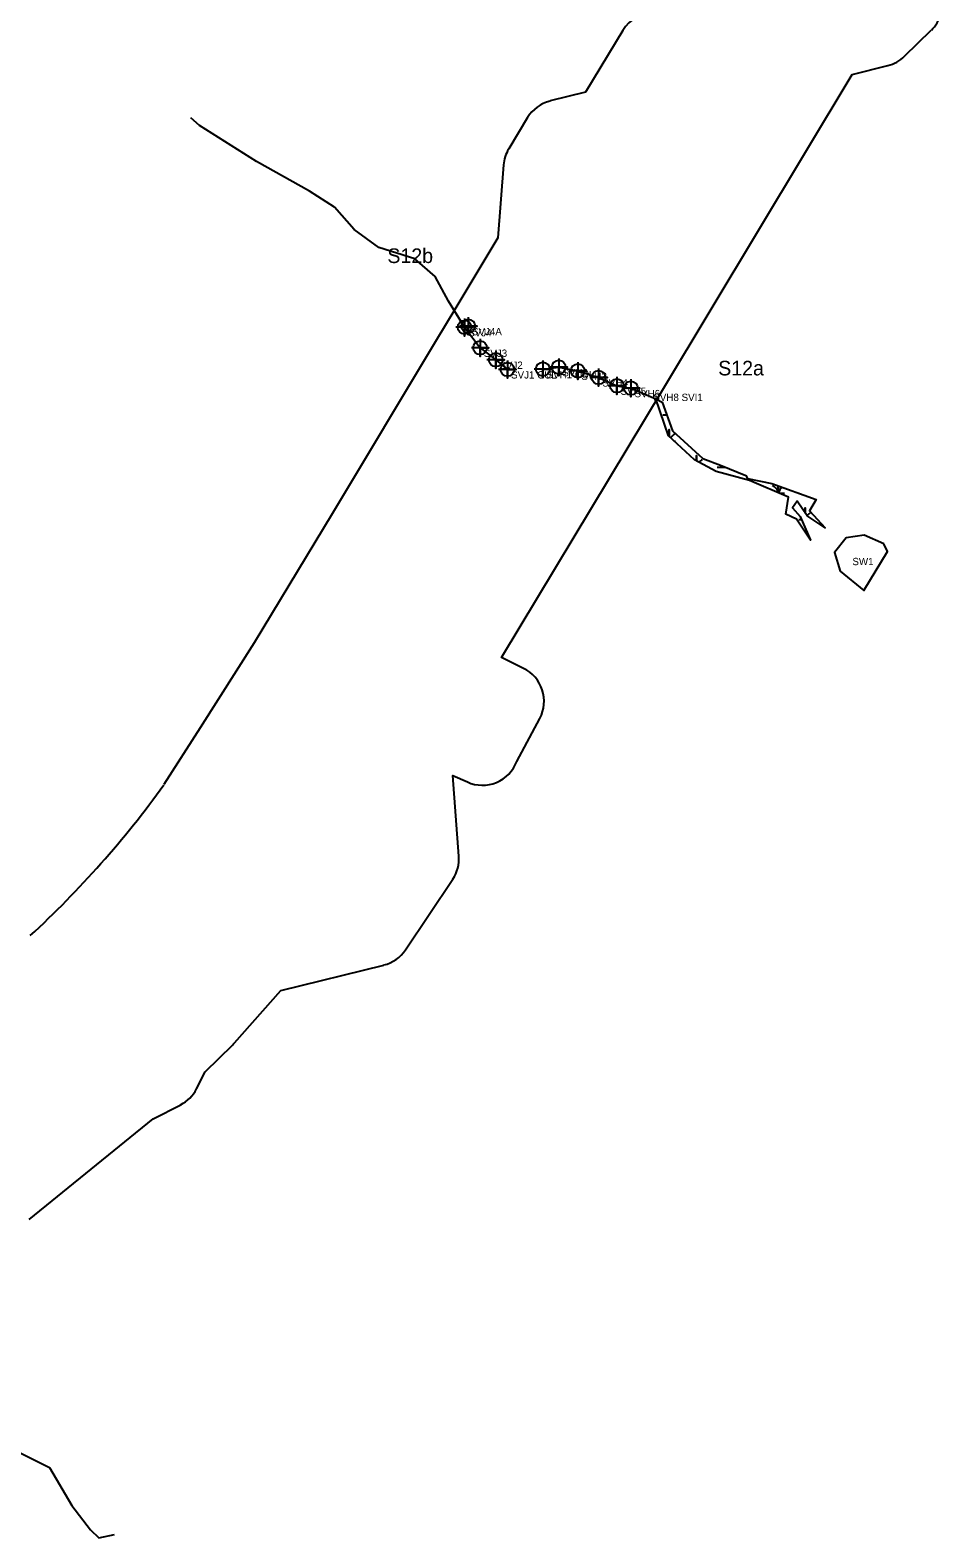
# Model space of a CAD drawing. Extents: x 1253697 to 1278588, y 912189 to 981699.
# Drawn here: x 1261249 to 1262493, y 917455 to 919517 of the extents above; entities that cross this region are included whole.
import ezdxf

# ---------------------------------------------------------------- set-up
doc = ezdxf.new("R2010")
doc.units = 0
for name, color, linetype in [('Default', 7, 'Continuous'), ('Exist Environmental Wetland Boundary', 7, 'Continuous'), ('Exist Hydro Jurisdictional Stream or Body of Water Mitigable', 7, 'Continuous'), ('Exist Hydro Jurisdictional Stream or Body of Water Mitigable Cogo Comment', 7, 'Continuous'), ('Exist Hydro Jurisdictional Stream or Body of Water Mitigable Cogo Number', 7, 'Continuous'), ('Exist Hydro Jurisdictional Stream or Body of Water Mitigable Cogo Point CELL', 7, 'Continuous')]:
    doc.layers.add(name, color=color, linetype=linetype)

msp = doc.modelspace()

# ---------------------------------------------------------------- linework, layer by layer
at = {"layer": 'Default'}
for p, q in [((1262443.9, 919481.7), (1262480.5, 919517.4)), ((1262443.9, 919481.7), (1262480.5, 919517.4)), ((1262443.9, 919481.7), (1262480.5, 919517.4)), ((1262443.9, 919481.7), (1262480.5, 919517.4)), ((1261928.6, 919397.8), (1261902.9, 919355)), ((1261928.6, 919397.8), (1261902.9, 919355)), ((1261928.6, 919397.8), (1261902.9, 919355)), ((1261928.6, 919397.8), (1261902.9, 919355)), ((1261913.9, 918517.1), (1261945.3, 918576.1)), ((1261913.9, 918517.1), (1261945.3, 918576.1)), ((1261913.9, 918517.1), (1261945.3, 918576.1)), ((1261913.9, 918517.1), (1261945.3, 918576.1)), ((1261481.1, 918563.1), (1261431.6, 918485.5)), ((1261481.1, 918563.1), (1261431.6, 918485.5)), ((1261481.1, 918563.1), (1261431.6, 918485.5)), ((1261481.1, 918563.1), (1261431.6, 918485.5)), ((1261761.8, 918259.6), (1261826.4, 918356.4)), ((1261761.8, 918259.6), (1261826.4, 918356.4)), ((1261761.8, 918259.6), (1261826.4, 918356.4)), ((1261761.8, 918259.6), (1261826.4, 918356.4))]:
    msp.add_line(p, q, dxfattribs=at)
for points in [[(1262058.7, 919517.1), (1262007.9, 919432.7), (1261959.4, 919420.6)], [(1262058.7, 919517.1), (1262007.9, 919432.7), (1261959.4, 919420.6)], [(1262058.7, 919517.1), (1262007.9, 919432.7), (1261959.4, 919420.6)], [(1262058.7, 919517.1), (1262007.9, 919432.7), (1261959.4, 919420.6)], [(1261923.1, 918644.5), (1261893, 918659.2), (1262114.3, 919027.3), (1262372.5, 919456.9), (1262421, 919469)], [(1261923.1, 918644.5), (1261893, 918659.2), (1262114.3, 919027.3), (1262372.5, 919456.9), (1262421, 919469)], [(1261923.1, 918644.5), (1261893, 918659.2), (1262114.3, 919027.3), (1262372.5, 919456.9), (1262421, 919469)], [(1261923.1, 918644.5), (1261893, 918659.2), (1262114.3, 919027.3), (1262372.5, 919456.9), (1262421, 919469)], [(1261895.9, 919333.1), (1261888.1, 919233.4), (1261830.5, 919137.5)], [(1261895.9, 919333.1), (1261888.1, 919233.4), (1261830.5, 919137.5)], [(1261895.9, 919333.1), (1261888.1, 919233.4), (1261830.5, 919137.5)], [(1261895.9, 919333.1), (1261888.1, 919233.4), (1261830.5, 919137.5)], [(1261830.5, 919137.5), (1261802.8, 919091.4), (1261661.4, 918856.1), (1261555.1, 918679.4), (1261481.1, 918563.1)], [(1261830.5, 919137.5), (1261802.8, 919091.4), (1261661.4, 918856.1), (1261555.1, 918679.4), (1261481.1, 918563.1)], [(1261830.5, 919137.5), (1261802.8, 919091.4), (1261661.4, 918856.1), (1261555.1, 918679.4), (1261481.1, 918563.1)], [(1261830.5, 919137.5), (1261802.8, 919091.4), (1261661.4, 918856.1), (1261555.1, 918679.4), (1261481.1, 918563.1)], [(1261834.7, 918387.9), (1261826.6, 918498.2), (1261846.4, 918489.2)], [(1261834.7, 918387.9), (1261826.6, 918498.2), (1261846.4, 918489.2)], [(1261834.7, 918387.9), (1261826.6, 918498.2), (1261846.4, 918489.2)], [(1261834.7, 918387.9), (1261826.6, 918498.2), (1261846.4, 918489.2)], [(1261528.1, 918132.2), (1261591.5, 918204), (1261732.2, 918238.8)], [(1261528.1, 918132.2), (1261591.5, 918204), (1261732.2, 918238.8)], [(1261528.1, 918132.2), (1261591.5, 918204), (1261732.2, 918238.8)], [(1261528.1, 918132.2), (1261591.5, 918204), (1261732.2, 918238.8)], [(1261476.1, 918069.4), (1261488.1, 918092.6), (1261525.7, 918129.7)], [(1261476.1, 918069.4), (1261488.1, 918092.6), (1261525.7, 918129.7)], [(1261476.1, 918069.4), (1261488.1, 918092.6), (1261525.7, 918129.7)], [(1261476.1, 918069.4), (1261488.1, 918092.6), (1261525.7, 918129.7)], [(1261247.4, 917890.8), (1261416.8, 918028.6), (1261454.5, 918047.8)], [(1261247.4, 917890.8), (1261416.8, 918028.6), (1261454.5, 918047.8)], [(1261247.4, 917890.8), (1261416.8, 918028.6), (1261454.5, 918047.8)], [(1261247.4, 917890.8), (1261416.8, 918028.6), (1261454.5, 918047.8)]]:
    msp.add_lwpolyline(points, dxfattribs=at)
for centre, radius, start, end in [((1262101.6, 919491.4), 50, 88.969, 148.9907), ((1262101.6, 919491.4), 50, 88.969, 148.9907), ((1262101.6, 919491.4), 50, 88.969, 148.9907), ((1262101.6, 919491.4), 50, 88.969, 148.9907), ((1262445.6, 919553.2), 50, 314.297, 343.4141), ((1262445.6, 919553.2), 50, 314.297, 343.4141), ((1262445.6, 919553.2), 50, 314.297, 343.4141), ((1262445.6, 919553.2), 50, 314.297, 343.4141), ((1262408.9, 919517.5), 50, 283.9905, 314.297), ((1262408.9, 919517.5), 50, 283.9905, 314.297), ((1262408.9, 919517.5), 50, 283.9905, 314.297), ((1262408.9, 919517.5), 50, 283.9905, 314.297), ((1261971.5, 919372), 50, 103.9905, 148.9905), ((1261971.5, 919372), 50, 103.9905, 148.9905), ((1261971.5, 919372), 50, 103.9905, 148.9905), ((1261971.5, 919372), 50, 103.9905, 148.9905), ((1261945.7, 919329.2), 50, 148.9905, 175.5557), ((1261945.7, 919329.2), 50, 148.9905, 175.5557), ((1261945.7, 919329.2), 50, 148.9905, 175.5557), ((1261945.7, 919329.2), 50, 148.9905, 175.5557), ((1261873.4, 919111.8), 50, 148.9905, 148.9908), ((1261873.4, 919111.8), 50, 148.9905, 148.9908), ((1261901.2, 918599.6), 50, 331.9389, 64.0284), ((1261901.2, 918599.6), 50, 331.9389, 64.0284), ((1261901.2, 918599.6), 50, 331.9389, 64.0284), ((1261901.2, 918599.6), 50, 331.9389, 64.0284), ((1261523.2, 918536.3), 50, 147.48918145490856, 147.48922457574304), ((1261523.2, 918536.3), 50, 147.48918145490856, 147.48922457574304), ((1261867.1, 918534.7), 50, 245.6021, 339.4199), ((1261867.1, 918534.7), 50, 245.6021, 339.4199), ((1261867.1, 918534.7), 50, 245.6021, 339.4199), ((1261867.1, 918534.7), 50, 245.6021, 339.4199), ((1260334.6, 919272.3), 1350, 312.6253, 324.3503), ((1260334.6, 919272.3), 1350, 312.6253, 324.3503), ((1260334.6, 919272.3), 1350, 312.6253, 324.3503), ((1260334.6, 919272.3), 1350, 312.6253, 324.3503), ((1261784.9, 918384.2), 50, 326.2609, 4.2006), ((1261784.9, 918384.2), 50, 326.2609, 4.2006), ((1261784.9, 918384.2), 50, 326.2609, 4.2006), ((1261784.9, 918384.2), 50, 326.2609, 4.2006), ((1261720.2, 918287.4), 50, 283.9003, 326.2609), ((1261720.2, 918287.4), 50, 283.9003, 326.2609), ((1261720.2, 918287.4), 50, 283.9003, 326.2609), ((1261720.2, 918287.4), 50, 283.9003, 326.2609), ((1261490.6, 918165.3), 50, 314.6181, 318.5291), ((1261490.6, 918165.3), 50, 314.6181, 318.5291), ((1261490.6, 918165.3), 50, 314.6181, 318.5291), ((1261490.6, 918165.3), 50, 314.6181, 318.5291), ((1261431.7, 918092.3), 50, 297.0927, 332.7249), ((1261431.7, 918092.3), 50, 297.0927, 332.7249), ((1261431.7, 918092.3), 50, 297.0927, 332.7249), ((1261431.7, 918092.3), 50, 297.0927, 332.7249)]:
    msp.add_arc(centre, radius, start, end, dxfattribs=at)
at = {"layer": 'Exist Environmental Wetland Boundary'}
for p, q in [((1262113.6, 918991.3), (1262118.8, 918991.3)), ((1262129, 918955.5), (1262130.8, 918955.5)), ((1262271, 918885), (1262271, 918894.4)), ((1262271, 918894.4), (1262271, 918885)), ((1262273.4, 918884), (1262279.6, 918884)), ((1262299.6, 918884), (1262299.8, 918884)), ((1262299.6, 918848.2), (1262303.1, 918848.2))]:
    msp.add_line(p, q, dxfattribs=at)
msp.add_lwpolyline([(1262104, 919013.2), (1262112.5, 919008.5), (1262126.9, 918969.2), (1262168, 918931.8), (1262192.3, 918922.4), (1262227.1, 918908.4), (1262229.2, 918904.4), (1262262.4, 918897.5), (1262323.1, 918875.5), (1262314.2, 918859.8), (1262335.2, 918836.7), (1262310.6, 918853.3), (1262297.2, 918873.2), (1262290.7, 918864.2), (1262301.3, 918852.2), (1262315.5, 918820.1), (1262296.2, 918848.7), (1262281.7, 918855.3), (1262285.3, 918878.9), (1262232.1, 918901.5), (1262186.4, 918913.8), (1262156.6, 918929.8), (1262121.4, 918962.6)], close=True, dxfattribs=at)
for points in [[(1262122.2, 918961.8), (1262122.2, 918971.3), (1262122.2, 918961.8)], [(1262159.4, 918928.3), (1262159.4, 918935.5), (1262159.4, 918928.3)], [(1262188, 918919.7), (1262196.6, 918919.7), (1262196.6, 918920.7)], [(1262196.6, 918920.7), (1262196.6, 918919.7), (1262199, 918919.7)], [(1262308.2, 918856.8), (1262308.2, 918864), (1262308.2, 918856.8)]]:
    msp.add_lwpolyline(points, dxfattribs=at)
for centre, radius, start, end in [((1262109.9, 918990.4), 12.3, 65.334, 67.535), ((1262140.5, 918949.5), 19.2, 122.1274, 147.1173), ((1262177.7, 918913.7), 19.2, 122.1274, 139.0127), ((1262184.4, 918918.8), 12.3, 4.1403, 8.8357), ((1262214.9, 918913.7), 19.2, 158.9798, 161.6222), ((1262258.8, 918883.1), 12.3, 9.2309, 67.535), ((1262289.3, 918877.9), 19.2, 131.2568, 158.7903), ((1262326.5, 918842.1), 19.2, 123.75, 144.8055), ((1262326.5, 918806.3), 19.2, 127.4607, 128.3533)]:
    msp.add_arc(centre, radius, start, end, dxfattribs=at)
at = {"layer": 'Exist Hydro Jurisdictional Stream or Body of Water Mitigable'}
for points in [[(1261842.5, 919111.1), (1261820.5, 919146.9), (1261802.3, 919180.6), (1261774.4, 919204.6), (1261725.4, 919220), (1261691.6, 919244.7), (1261664.6, 919275.5), (1261630.7, 919297.4), (1261558.2, 919337.6), (1261480.4, 919387.1), (1261468.4, 919397.5)], [(1261828.4, 919134), (1261842.5, 919111.1), (1261863.8, 919083.1), (1261885.1, 919066.7), (1261901.1, 919053.5)], [(1261949.5, 919053.8), (1261971.2, 919056.5), (1261997.2, 919051.5), (1262025.7, 919042.5), (1262050.8, 919031.1), (1262069.9, 919027.9), (1262104, 919013.2), (1262104, 919013.2), (1262105.4, 919012.5)], [(1261142.6, 917705), (1261161.2, 917659.5), (1261188.8, 917594.5), (1261255.2, 917561.5), (1261275, 917551.7), (1261305.9, 917499.5), (1261331.1, 917466.4), (1261342.7, 917455.4), (1261364, 917459.9)]]:
    msp.add_lwpolyline(points, dxfattribs=at)
msp.add_lwpolyline([(1262415.5, 918814.8), (1262388.7, 918826.7), (1262364.2, 918822.9), (1262348.2, 918802.9), (1262355.7, 918777.3), (1262388.1, 918751.2), (1262420.5, 918804.6)], close=True, dxfattribs=at)
at = {"layer": 'Exist Hydro Jurisdictional Stream or Body of Water Mitigable Cogo Point CELL'}
for points in [[(1261842.5, 919123.1), (1261842.5, 919099.1), (1261842.5, 919111.1), (1261854.5, 919111.1), (1261830.5, 919111.1)], [(1261847.6, 919124.7), (1261847.6, 919100.7), (1261847.6, 919112.7), (1261859.6, 919112.7), (1261835.6, 919112.7)], [(1261863.8, 919095.1), (1261863.8, 919071.1), (1261863.8, 919083.1), (1261875.8, 919083.1), (1261851.8, 919083.1)], [(1261885.1, 919078.7), (1261885.1, 919054.7), (1261885.1, 919066.7), (1261897.1, 919066.7), (1261873.1, 919066.7)], [(1261901.1, 919065.5), (1261901.1, 919041.5), (1261901.1, 919053.5), (1261913.1, 919053.5), (1261889.1, 919053.5)], [(1261949.5, 919065.8), (1261949.5, 919041.8), (1261949.5, 919053.8), (1261961.5, 919053.8), (1261937.5, 919053.8)], [(1261971.2, 919068.5), (1261971.2, 919044.5), (1261971.2, 919056.5), (1261983.2, 919056.5), (1261959.2, 919056.5)], [(1261997.2, 919063.5), (1261997.2, 919039.5), (1261997.2, 919051.5), (1262009.2, 919051.5), (1261985.2, 919051.5)], [(1262025.7, 919054.5), (1262025.7, 919030.5), (1262025.7, 919042.5), (1262037.7, 919042.5), (1262013.7, 919042.5)], [(1262050.8, 919043.1), (1262050.8, 919019.1), (1262050.8, 919031.1), (1262062.8, 919031.1), (1262038.8, 919031.1)], [(1262069.9, 919039.9), (1262069.9, 919015.9), (1262069.9, 919027.9), (1262081.9, 919027.9), (1262057.9, 919027.9)]]:
    msp.add_lwpolyline(points, dxfattribs=at)
for centre in [(1261842.5, 919111.1), (1261847.6, 919112.7), (1261863.8, 919083.1), (1261885.1, 919066.7), (1261949.5, 919053.8), (1261971.2, 919056.5), (1261901.1, 919053.5), (1261997.2, 919051.5), (1262025.7, 919042.5), (1262050.8, 919031.1), (1262069.9, 919027.9)]:
    msp.add_circle(centre, 9.38, dxfattribs=at)

# ---------------------------------------------------------------- texts
at = {"layer": 'Exist Hydro Jurisdictional Stream or Body of Water Mitigable'}
msp.add_text('SW1', height=10, dxfattribs=at).set_placement((1262372.6, 918785.7))
at = {"layer": 'Exist Hydro Jurisdictional Stream or Body of Water Mitigable Cogo Comment'}
for s, p in [('SVJ4', (1261847.5, 919098.6)), ('SVJ4A', (1261852.6, 919100.2)), ('SVJ3', (1261868.8, 919070.6)), ('SVJ2', (1261890.1, 919054.2)), ('SVJ1 CUL', (1261906.1, 919041)), ('SVH1 CUL', (1261954.5, 919041.3)), ('SVH2', (1261976.2, 919044)), ('SVH3', (1262002.2, 919039)), ('SVH4', (1262030.7, 919030)), ('SVH5', (1262055.8, 919018.6)), ('SVH6', (1262074.9, 919015.4)), ('SVH8 SVI1', (1262100.5, 919010.2))]:
    msp.add_text(s, height=10, dxfattribs=at).set_placement(p)
at = {"layer": 'Exist Hydro Jurisdictional Stream or Body of Water Mitigable Cogo Number'}
for s, p in [('S12b', (1261737, 919198.9)), ('S12a', (1262189.2, 919045.2))]:
    msp.add_text(s, height=20, dxfattribs=at).set_placement(p)

doc.saveas('drawing.dxf')
